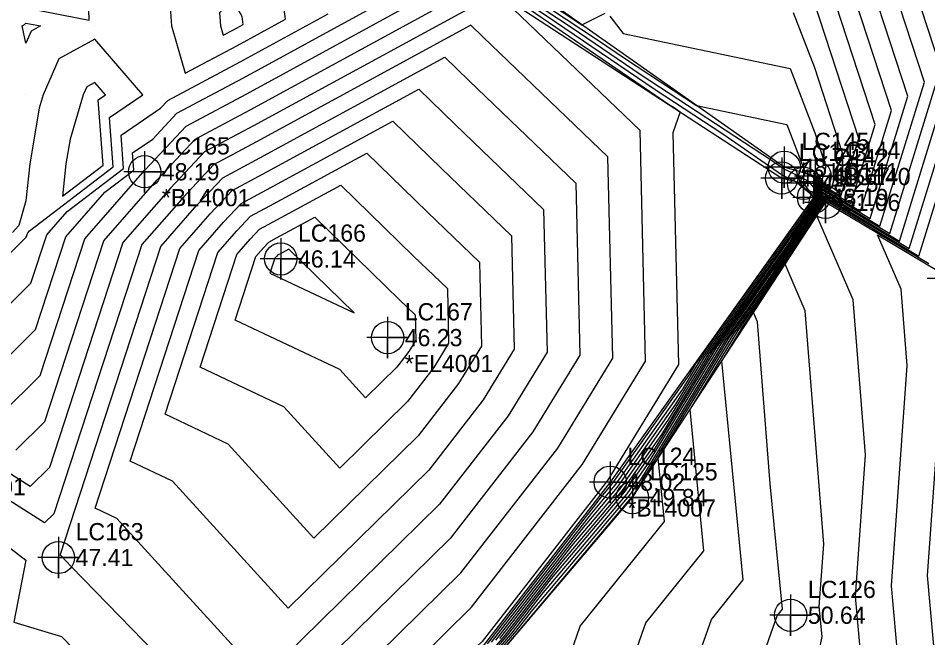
# Model space of a CAD drawing. Extents: x 2188792 to 2191981, y 386090 to 389710.
# Drawn here: x 2189959 to 2190090.9, y 387611.4 to 387701.3 of the extents above; entities that cross this region are included whole.
import ezdxf

# ---------------------------------------------------------------- set-up
doc = ezdxf.new("R2010")
doc.units = 0
for name, color, linetype in [('DTM Contours Major', 7, 'Continuous'), ('DTM Contours Minor', 7, 'Continuous'), ('Exist DTM Breakline', 7, 'Continuous'), ('Exist DTM Breakline Cogo Elevation', 7, 'Continuous'), ('Exist DTM Breakline Cogo Number', 7, 'Continuous'), ('Exist DTM Breakline Cogo Point CELL', 7, 'Continuous'), ('Exist DTM Breakline Underwater', 7, 'Continuous'), ('Exist DTM Breakline Underwater Cogo Comment', 7, 'Continuous'), ('Exist DTM Breakline Underwater Cogo Elevation', 7, 'Continuous'), ('Exist DTM Breakline Underwater Cogo Number', 7, 'Continuous'), ('Exist DTM Breakline Underwater Cogo Point CELL', 7, 'Continuous'), ('Exist DTM QL2 LIDAR Elevation Point', 7, 'Continuous'), ('Exist DTM Regular Point Underwater CELL', 7, 'Continuous'), ('Exist DTM Regular Point Underwater Cogo Comment', 7, 'Continuous'), ('Exist DTM Regular Point Underwater Cogo Elevation', 7, 'Continuous'), ('Exist DTM Regular Point Underwater Cogo Number', 7, 'Continuous')]:
    doc.layers.add(name, color=color, linetype=linetype)

msp = doc.modelspace()

# ---------------------------------------------------------------- linework, layer by layer
at = {"layer": 'DTM Contours Major'}
for points in [[(2190038.64, 387607.77), (2190040.51, 387613.08), (2190052.74, 387628.26), (2190051.83, 387637.48), (2190062.79, 387655.5), (2190066.78, 387661.14), (2190075.43, 387674.83), (2190075.4, 387676.25), (2190083.98, 387671.12), (2190090.42, 387692.01), (2190074.2, 387741.66), (2190073.77, 387742.76), (2190070.93, 387743.36), (2190067.33, 387747.99), (2190072.81, 387749.91), (2190076.45, 387752.04), (2190123.9, 387772)], [(2189979.14, 387677.85), (2189984.68, 387683.75), (2189992.62, 387687.98), (2190022.39, 387704.24), (2190022.13, 387706.16), (2190018.69, 387711.88), (2190024.66, 387708.09), (2190028.69, 387705.54), (2190032.06, 387703.31), (2190053.47, 387688.73), (2190053.97, 387688.41), (2190055.02, 387687.68), (2190053.94, 387684.64), (2190054.75, 387651.06), (2190044.44, 387634.23), (2190026.28, 387610.83), (2190025.48, 387610.05), (2190010.8, 387591.13), (2189995.27, 387571.63), (2189973.27, 387580.1), (2189966.15, 387587.41), (2189944.82, 387593.84)], [(2189990.23, 387699.6), (2189991.63, 387700.36), (2189991.47, 387701.54), (2189990.11, 387703.93), (2189988.21, 387702.07), (2189988.34, 387700.17), (2189988.74, 387698.81), (2189990.23, 387699.6)], [(2190071.4, 387702.13), (2190074.47, 387694.14), (2190078.51, 387681.77), (2190076.91, 387676.57), (2190074.77, 387677.85), (2190074.83, 387675.08), (2190070.95, 387668.95), (2190059.71, 387653.07), (2190052.31, 387640.9), (2190046.59, 387632.76), (2190037.78, 387622.35), (2190029.4, 387611.55), (2190018.74, 387598.97)], [(2189970.58, 387689.43), (2189971.66, 387690.17), (2189970.1, 387691.98), (2189968.94, 387691.34), (2189968.43, 387690.17), (2189966.52, 387683.76), (2189965.92, 387680.17), (2189965.4, 387675.47), (2189971.3, 387679.98), (2189970.58, 387689.43)], [(2189975.22, 387637.01), (2189985.19, 387667.58), (2189988.77, 387671.68), (2189991.33, 387674.41), (2189995.01, 387676.37), (2190013.32, 387686.36), (2190020.36, 387679.49), (2190030.54, 387669.7), (2190030.94, 387653.25), (2190026.45, 387645.92), (2190018.54, 387635.73), (2189998.15, 387615.68), (2189981.38, 387634.1), (2189975.22, 387637.01)], [(2189958.65, 387638.6), (2189962.84, 387642.77), (2189971.4, 387669), (2189979.14, 387677.85)], [(2190081.3, 387607.7), (2190080.41, 387617.39), (2190081.89, 387637.92), (2190080.1, 387660.4), (2190074.8, 387672.63), (2190076.04, 387674.59), (2190076.04, 387674.66), (2190091.05, 387665.68)]]:
    msp.add_lwpolyline(points, dxfattribs=at)
at = {"layer": 'DTM Contours Minor'}
for points in [[(2190015.59, 387594.34), (2190030.61, 387612.08), (2190034.89, 387617.6), (2190047.3, 387632.27), (2190050.28, 387636.51), (2190060.94, 387654.04), (2190069.28, 387665.82), (2190075.07, 387674.98), (2190075.02, 387677.21), (2190079.74, 387674.39), (2190083.28, 387685.87), (2190074.36, 387713.15), (2190072.35, 387718.38), (2190058.84, 387721.23), (2190041.72, 387743.25), (2190067.78, 387752.35), (2190085.09, 387762.49), (2190114.34, 387774.79)], [(2190014.01, 387592.03), (2190031.21, 387612.34), (2190033.44, 387615.22), (2190047.65, 387632.02), (2190049.27, 387634.32), (2190061.55, 387654.53), (2190068.45, 387664.26), (2190075.19, 387674.93), (2190075.15, 387676.89), (2190081.15, 387673.3), (2190085.66, 387687.92), (2190074.31, 387722.65), (2190072.82, 387726.51), (2190062.87, 387728.6), (2190050.26, 387744.83), (2190069.46, 387751.53), (2190082.21, 387759.01), (2190117.52, 387773.86)], [(2190015.34, 387593.15), (2190031.81, 387612.6), (2190032, 387612.85), (2190048.01, 387631.78), (2190048.26, 387632.13), (2190062.17, 387655.01), (2190067.61, 387662.7), (2190075.31, 387674.88), (2190075.28, 387676.57), (2190082.56, 387672.21), (2190088.04, 387689.97), (2190074.25, 387732.16), (2190073.3, 387734.64), (2190066.9, 387735.98), (2190058.79, 387746.41), (2190071.14, 387750.72), (2190079.33, 387755.52), (2190120.71, 387772.93)], [(2190041.43, 387531.48), (2190058.13, 387555.18), (2190058.15, 387555.2), (2190058.84, 387556.18), (2190061.26, 387559.53), (2190075.95, 387580.97), (2190076.83, 387582.19), (2190085.08, 387594.3), (2190087.02, 387603.83), (2190085.63, 387618.91), (2190087.94, 387650.88), (2190087.05, 387661.98), (2190083.64, 387669.87), (2190092.46, 387664.59), (2190104.71, 387704.3), (2190094.61, 387735.22), (2190126.33, 387750.03), (2190141.35, 387755.07), (2190142.39, 387756.18), (2190147.5, 387770.18)], [(2190046.11, 387602.43), (2190050.04, 387613.57), (2190058.45, 387624.01), (2190056.43, 387644.51), (2190063.4, 387655.99), (2190065.94, 387659.58), (2190075.55, 387674.78), (2190075.53, 387675.94), (2190085.39, 387670.03), (2190092.8, 387694.06), (2190074.94, 387748.71), (2190083.92, 387752.91), (2190127.09, 387771.06)], [(2190053.57, 387597.09), (2190059.56, 387614.06), (2190064.15, 387619.77), (2190061.02, 387651.54), (2190064.02, 387656.47), (2190065.11, 387658.01), (2190075.67, 387674.73), (2190075.66, 387675.62), (2190086.81, 387668.95), (2190095.19, 387696.11), (2190078.88, 387746.01), (2190130.07, 387769.93)], [(2190042.57, 387532.51), (2190058.4, 387554.98), (2190058.42, 387555), (2190059.07, 387555.94), (2190062.3, 387560.41), (2190076.2, 387580.7), (2190077.94, 387583.1), (2190090.49, 387601.51), (2190092.34, 387604.26), (2190090.85, 387620.43), (2190093.94, 387663.26), (2190094.29, 387663.29), (2190094.14, 387663.45), (2190094.08, 387663.52), (2190094.05, 387663.55), (2190094.03, 387663.57), (2190093.95, 387663.75), (2190107.1, 387706.35), (2190098.54, 387732.52), (2190125.39, 387745.06), (2190141.26, 387750.38), (2190143.63, 387752.53), (2190146.17, 387752.53), (2190150.45, 387767.81)], [(2189984.53, 387532.74), (2189985.31, 387544.52), (2189983.47, 387548.8), (2189986.68, 387548.09), (2189986.91, 387548.12), (2189997.2, 387555.6), (2189997.78, 387556.13), (2189998.07, 387556.59), (2190001.81, 387564.06), (2190025.83, 387576.7), (2190028.7, 387578.21), (2190035.67, 387586.74), (2190061.03, 387591.74), (2190069.08, 387614.56), (2190069.86, 387615.53), (2190068.06, 387633.74), (2190066.2, 387657.23), (2190065.62, 387658.57), (2190075.79, 387674.68), (2190075.78, 387675.3), (2190088.22, 387667.86), (2190097.57, 387698.16), (2190082.81, 387743.31), (2190129.14, 387764.96)], [(2190027.25, 387517.33), (2189992.67, 387537.32), (2189992.48, 387538.02), (2189991.94, 387551.2), (2189998.06, 387555.65), (2189998.2, 387555.78), (2189998.27, 387555.89), (2189999.16, 387557.66), (2190031.13, 387574.49), (2190032.74, 387575.34), (2190036.65, 387580.11), (2190068.49, 387586.4), (2190073.13, 387599.54), (2190075.58, 387611.58), (2190075.18, 387615.87), (2190075.84, 387624.97), (2190073.15, 387658.81), (2190070.21, 387665.6), (2190075.92, 387674.64), (2190075.91, 387674.98), (2190089.63, 387666.77), (2190099.95, 387700.2), (2190086.74, 387740.62), (2190128.2, 387759.98)], [(2189983.35, 387685.62), (2189992.14, 387690.3), (2190016.23, 387703.46), (2190015.73, 387707.32), (2190008.8, 387718.85), (2190020.82, 387711.23), (2190028.92, 387706.09), (2190035.7, 387701.6), (2190051.35, 387690.95), (2190061.18, 387684.5), (2190069.82, 387678.52), (2190071.79, 387677.6), (2190074.07, 387675.65), (2190074.34, 387675.35), (2190074.34, 387675.27), (2190074.29, 387675.19), (2190057.24, 387651.13), (2190056.35, 387649.66), (2190045.16, 387633.75), (2190043.56, 387631.86), (2190026.99, 387610.5)], [(2189960.1, 387702.77), (2189969.28, 387700.99), (2189968.99, 387710.17)], [(2189980.56, 387709.72), (2189981.23, 387700.17), (2189983.23, 387693.29), (2189990.7, 387697.27), (2189997.78, 387701.14), (2189997, 387707.06)], [(2190029.38, 387707.19), (2190042.99, 387698.17), (2190047.09, 387695.38), (2190057.38, 387688.63), (2190070.45, 387685.88), (2190073.18, 387678.78), (2190074.29, 387678.21), (2190074.53, 387677.94), (2190074.59, 387675.18), (2190072.62, 387672.07), (2190058.47, 387652.1), (2190054.33, 387645.28), (2190045.87, 387633.26), (2190040.67, 387627.11), (2190028.2, 387611.03)], [(2190029.61, 387707.74), (2190040.76, 387700.35), (2190044.12, 387702.04)], [(2190029.15, 387706.64), (2190039.34, 387699.88), (2190049.22, 387693.16), (2190068.39, 387680.59), (2190070.04, 387679.45), (2190070.75, 387679.11), (2190073.49, 387677.71), (2190074.44, 387676.64), (2190074.47, 387675.22), (2190073.46, 387673.63), (2190057.86, 387651.61), (2190055.34, 387647.47), (2190045.52, 387633.51), (2190042.12, 387629.48), (2190027.59, 387610.76)], [(2190028.41, 387704.94), (2189993.1, 387685.66), (2189986.01, 387681.88), (2189981.07, 387676.62), (2189974.16, 387668.72), (2189963.51, 387636.08), (2189960.74, 387633.32), (2189946.06, 387642.63)], [(2189951.6, 387603.73), (2189965.7, 387599.48), (2189978.67, 387586.18), (2189994.77, 387579.98), (2190006.14, 387594.25), (2190016.89, 387608.1), (2190024.73, 387615.81), (2190040.84, 387636.57), (2190049.99, 387651.5), (2190049.18, 387684.99), (2190028.44, 387704.92), (2190028.41, 387704.94)], [(2190017.17, 387596.65), (2190030, 387611.81), (2190036.33, 387619.98), (2190046.94, 387632.52), (2190051.29, 387638.7), (2190060.32, 387653.56), (2190070.12, 387667.38), (2190074.95, 387675.03), (2190074.9, 387677.53), (2190078.32, 387675.48), (2190080.89, 387683.82), (2190074.42, 387703.64)], [(2189980.68, 387689.36), (2189991.18, 387694.95), (2190003.93, 387701.91)], [(2189982.01, 387687.49), (2189991.66, 387692.63), (2190010.08, 387702.69)], [(2190044.82, 387701.57), (2190046.74, 387699.09), (2190070.93, 387694.01), (2190074.53, 387684.64), (2190076.13, 387679.73), (2190075.49, 387677.66), (2190074.65, 387678.17), (2190074.71, 387675.13), (2190071.79, 387670.51), (2190059.09, 387652.58), (2190053.32, 387643.09), (2190046.23, 387633.01), (2190039.23, 387624.73), (2190028.8, 387611.29)], [(2189943.41, 387635.49), (2189960.09, 387622.64), (2189958.38, 387613.63), (2189965.25, 387611.56), (2189984.07, 387592.26), (2189994.27, 387588.33), (2190001.48, 387597.37), (2190008.3, 387606.15), (2190023.19, 387620.79), (2190037.25, 387638.91), (2190045.22, 387651.94), (2190044.52, 387681.17), (2190026.42, 387698.56), (2190024.64, 387700.3)], [(2190024.64, 387700.3), (2189993.57, 387683.33), (2189987.34, 387680.02), (2189983, 387675.38), (2189976.92, 387668.44), (2189964.18, 387629.39), (2189962.83, 387628.05), (2189945.26, 387639.18)], [(2189960.1, 387697.69), (2189959.58, 387700.17), (2189959.9, 387700.38), (2189960.1, 387700.58), (2189962.22, 387700.17), (2189960.86, 387699.42), (2189960.1, 387697.69)], [(2189960.37, 387670.14), (2189960.63, 387670.44), (2189972.78, 387679.74), (2189972.25, 387686.86), (2189977.05, 387690.17), (2189970.1, 387698.26), (2189964.9, 387695.38), (2189962.62, 387690.17), (2189962.04, 387688.23), (2189960.69, 387680.17), (2189960.1, 387674.77), (2189959.09, 387671.19), (2189958.17, 387670.17)], [(2189965.07, 387623.37), (2189979.68, 387668.15), (2189984.92, 387674.15), (2189988.67, 387678.15), (2189994.05, 387681.01), (2190020.87, 387695.65), (2190024.4, 387692.21), (2190039.86, 387677.35), (2190040.46, 387652.38), (2190033.65, 387641.25), (2190021.64, 387625.77), (2189999.71, 387604.21), (2189996.83, 387600.5), (2189993.78, 387596.67), (2189989.46, 387598.33), (2189966.65, 387621.74), (2189965.22, 387623.3), (2189965.07, 387623.37)], [(2189970.15, 387630.19), (2189982.43, 387667.87), (2189986.85, 387672.91), (2189990, 387676.28), (2189994.53, 387678.69), (2190017.09, 387691.01), (2190022.38, 387685.85), (2190035.2, 387673.53), (2190035.7, 387652.81), (2190030.05, 387643.58), (2190020.09, 387630.75), (2189994.42, 387605.51), (2189973.3, 387628.7), (2189970.15, 387630.19)], [(2189952.38, 387654.42), (2189960.84, 387662.83), (2189963.13, 387669.86), (2189966.09, 387673.24), (2189974.27, 387679.5), (2189973.91, 387684.3), (2189979.62, 387688.23), (2189980.68, 387689.36)], [(2189954.47, 387649.15), (2189961.51, 387656.14), (2189965.89, 387669.57), (2189971.55, 387676.04), (2189975.76, 387679.26), (2189975.57, 387681.73), (2189978.51, 387683.76), (2189982.01, 387687.49)], [(2189956.56, 387643.87), (2189962.18, 387649.46), (2189968.64, 387669.29), (2189977, 387678.84), (2189977.24, 387679.03), (2189977.23, 387679.17), (2189977.4, 387679.28), (2189983.35, 387685.62)], [(2189980.29, 387643.82), (2189987.95, 387667.3), (2189990.7, 387670.44), (2189992.67, 387672.54), (2189995.49, 387674.04), (2190009.55, 387681.72), (2190018.34, 387673.13), (2190025.89, 387665.88), (2190026.18, 387653.69), (2190022.85, 387648.26), (2190016.99, 387640.7), (2190001.88, 387625.85), (2189989.46, 387639.5), (2189980.29, 387643.82)], [(2189985.37, 387650.64), (2189990.71, 387667.02), (2189992.63, 387669.21), (2189994, 387670.67), (2189995.97, 387671.72), (2190005.77, 387677.07), (2190016.32, 387666.77), (2190021.23, 387662.06), (2190021.42, 387654.13), (2190019.26, 387650.6), (2190015.44, 387645.68), (2190005.62, 387636.02), (2189997.54, 387644.9), (2189985.37, 387650.64)], [(2189990.44, 387657.46), (2189993.47, 387666.73), (2189994.55, 387667.97), (2189995.33, 387668.8), (2189996.44, 387669.4), (2190002, 387672.43), (2190014.3, 387660.41), (2190016.57, 387658.23), (2190016.66, 387654.57), (2190015.66, 387652.93), (2190013.89, 387650.66), (2190009.35, 387646.2), (2190005.62, 387650.3), (2189990.44, 387657.46)], [(2189950.29, 387659.7), (2189960.17, 387669.52), (2189960.37, 387670.14)], [(2190007.7, 387658.52), (2189998.23, 387667.78), (2189996.92, 387667.07), (2189996.66, 387666.93), (2189996.48, 387666.74), (2189996.22, 387666.45), (2189995.51, 387664.27), (2190007.7, 387658.52)]]:
    msp.add_lwpolyline(points, dxfattribs=at)
at = {"layer": 'Exist DTM Breakline'}
msp.add_lwpolyline([(2189920.87, 387592.29), (2189962.12, 387565.38), (2189980.08, 387549.91), (2189986.9, 387547.68), (2189998.33, 387555.67), (2190012.46, 387589.75), (2190048.08, 387631.73), (2190076.07, 387674.57), (2190074.56, 387678.38), (2190070.09, 387679.67), (2190029.77, 387708.1), (2190010.73, 387719.44), (2190038.07, 387742.58)], dxfattribs=at)
at = {"layer": 'Exist DTM Breakline Cogo Point CELL'}
for points in [[(2190070.09, 387682.67), (2190070.09, 387676.67), (2190070.09, 387679.67), (2190073.09, 387679.67), (2190067.09, 387679.67)], [(2190074.56, 387681.38), (2190074.56, 387675.38), (2190074.56, 387678.38), (2190077.56, 387678.38), (2190071.56, 387678.38)], [(2190076.07, 387677.57), (2190076.07, 387671.57), (2190076.07, 387674.57), (2190079.07, 387674.57), (2190073.07, 387674.57)], [(2190048.08, 387634.73), (2190048.08, 387628.73), (2190048.08, 387631.73), (2190051.08, 387631.73), (2190045.08, 387631.73)]]:
    msp.add_lwpolyline(points, dxfattribs=at)
for centre in [(2190070.09, 387679.67), (2190074.56, 387678.38), (2190076.07, 387674.57), (2190048.08, 387631.73)]:
    msp.add_circle(centre, 2.34, dxfattribs=at)
at = {"layer": 'Exist DTM Breakline Underwater'}
for points in [[(2190032.68, 387744.51), (2190008.78, 387718.87), (2190028.46, 387705), (2190069.72, 387678.09), (2190072.89, 387677.33), (2190074.34, 387675.28), (2190044.85, 387633.97)], [(2190044.85, 387633.97), (2190011.33, 387590.77), (2189992.7, 387560.38), (2189987.06, 387555.03), (2189983.21, 387554.53), (2189966.7, 387572.69), (2189926.49, 387599.24)]]:
    msp.add_lwpolyline(points, dxfattribs=at)
at = {"layer": 'Exist DTM Breakline Underwater Cogo Point CELL'}
for points in [[(2190069.72, 387681.09), (2190069.72, 387675.09), (2190069.72, 387678.09), (2190072.72, 387678.09), (2190066.72, 387678.09)], [(2190072.89, 387680.33), (2190072.89, 387674.33), (2190072.89, 387677.33), (2190075.89, 387677.33), (2190069.89, 387677.33)], [(2190074.34, 387678.28), (2190074.34, 387672.28), (2190074.34, 387675.28), (2190077.34, 387675.28), (2190071.34, 387675.28)], [(2190044.85, 387636.97), (2190044.85, 387630.97), (2190044.85, 387633.97), (2190047.85, 387633.97), (2190041.85, 387633.97)]]:
    msp.add_lwpolyline(points, dxfattribs=at)
for centre in [(2190069.72, 387678.09), (2190072.89, 387677.33), (2190074.34, 387675.28), (2190044.85, 387633.97)]:
    msp.add_circle(centre, 2.34, dxfattribs=at)
at = {"layer": 'Exist DTM QL2 LIDAR Elevation Point'}
for p, q in [((2189960.1, 387700.17), (2189960.1, 387700.17)), ((2189970.1, 387700.17), (2189970.1, 387700.17)), ((2189980.11, 387700.17), (2189980.11, 387700.17)), ((2189990.11, 387700.17), (2189990.11, 387700.17)), ((2189960.1, 387690.17), (2189960.1, 387690.17)), ((2189970.1, 387690.17), (2189970.1, 387690.17)), ((2189980.11, 387690.17), (2189980.11, 387690.17)), ((2189960.1, 387680.17), (2189960.1, 387680.17)), ((2189970.1, 387680.17), (2189970.1, 387680.17)), ((2189960.1, 387670.17), (2189960.1, 387670.17))]:
    msp.add_line(p, q, dxfattribs=at)
at = {"layer": 'Exist DTM Regular Point Underwater CELL'}
for points in [[(2189977.33, 387682.01), (2189977.33, 387676.01), (2189977.33, 387679.01), (2189980.33, 387679.01), (2189974.33, 387679.01)], [(2189997.07, 387669.36), (2189997.07, 387663.36), (2189997.07, 387666.36), (2190000.07, 387666.36), (2189994.07, 387666.36)], [(2190093.84, 387666.52), (2190093.84, 387660.52), (2190093.84, 387663.52), (2190096.84, 387663.52), (2190090.84, 387663.52)], [(2190012.56, 387657.94), (2190012.56, 387651.94), (2190012.56, 387654.94), (2190015.56, 387654.94), (2190009.56, 387654.94)], [(2189964.82, 387626.03), (2189964.82, 387620.03), (2189964.82, 387623.03), (2189967.82, 387623.03), (2189961.82, 387623.03)], [(2190071.02, 387617.66), (2190071.02, 387611.66), (2190071.02, 387614.66), (2190074.02, 387614.66), (2190068.02, 387614.66)]]:
    msp.add_lwpolyline(points, dxfattribs=at)
for centre in [(2189977.33, 387679.01), (2189997.07, 387666.36), (2190012.56, 387654.94), (2189964.82, 387623.03), (2190071.02, 387614.66)]:
    msp.add_circle(centre, 2.34, dxfattribs=at)

# ---------------------------------------------------------------- texts
at = {"layer": 'Exist DTM Breakline Cogo Elevation'}
for s, p in [('48.45', (2190072.59, 387678.42)), ('48.67', (2190077.06, 387677.13)), ('51.06', (2190078.57, 387673.32)), ('49.84', (2190050.58, 387630.48))]:
    msp.add_text(s, height=2.5, dxfattribs=at).set_placement(p)
at = {"layer": 'Exist DTM Breakline Cogo Number'}
for s, p in [('LC145', (2190072.59, 387682.17)), ('LC144', (2190077.06, 387680.88)), ('LC140', (2190078.57, 387677.07)), ('LC125', (2190050.58, 387634.23))]:
    msp.add_text(s, height=2.5, dxfattribs=at).set_placement(p)
at = {"layer": 'Exist DTM Breakline Underwater Cogo Comment'}
msp.add_text('*BL4007', height=2.5, dxfattribs=at).set_placement((2190047.35, 387628.97))
at = {"layer": 'Exist DTM Breakline Underwater Cogo Elevation'}
for s, p in [('48.11', (2190072.22, 387676.84)), ('48.25', (2190075.39, 387676.08)), ('48.19', (2190076.84, 387674.03)), ('48.02', (2190047.35, 387632.72))]:
    msp.add_text(s, height=2.5, dxfattribs=at).set_placement(p)
at = {"layer": 'Exist DTM Breakline Underwater Cogo Number'}
for s, p in [('LC143', (2190072.22, 387680.59)), ('LC142', (2190075.39, 387679.83)), ('LC141', (2190076.84, 387677.78)), ('LC124', (2190047.35, 387636.47))]:
    msp.add_text(s, height=2.5, dxfattribs=at).set_placement(p)
at = {"layer": 'Exist DTM Regular Point Underwater Cogo Comment'}
for s, p in [('*BL4001', (2189979.83, 387674.01)), ('*EL4001', (2190015.06, 387649.94)), ('*EL4001', (2189947.27, 387632.06))]:
    msp.add_text(s, height=2.5, dxfattribs=at).set_placement(p)
at = {"layer": 'Exist DTM Regular Point Underwater Cogo Elevation'}
for s, p in [('48.19', (2189979.83, 387677.76)), ('46.14', (2189999.57, 387665.11)), ('46.23', (2190015.06, 387653.69)), ('47.41', (2189967.32, 387621.78)), ('50.64', (2190073.52, 387613.41))]:
    msp.add_text(s, height=2.5, dxfattribs=at).set_placement(p)
at = {"layer": 'Exist DTM Regular Point Underwater Cogo Number'}
for s, p in [('LC165', (2189979.83, 387681.51)), ('LC166', (2189999.57, 387668.86)), ('LC167', (2190015.06, 387657.44)), ('LC163', (2189967.32, 387625.53)), ('LC126', (2190073.52, 387617.16))]:
    msp.add_text(s, height=2.5, dxfattribs=at).set_placement(p)

doc.saveas('drawing.dxf')
